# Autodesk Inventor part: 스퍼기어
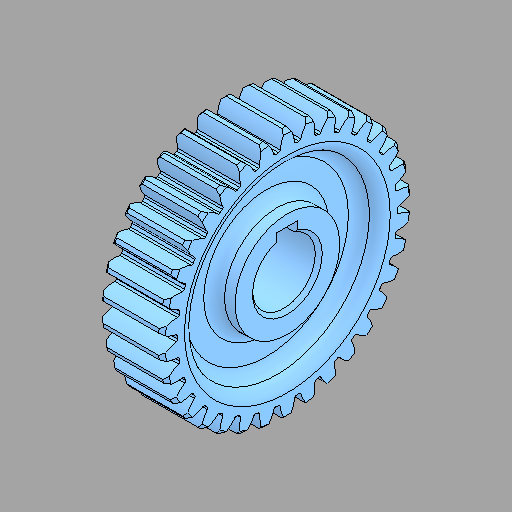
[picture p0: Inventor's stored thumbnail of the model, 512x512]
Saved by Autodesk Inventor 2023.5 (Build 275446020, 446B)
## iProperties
Created: 2025-07
Part Number: 스퍼기어
Material: 강철, 합금
Document SubType Name: Modeling
Designer: 1강의실14
Density: 7.73 g/cm^3
Appearance: 기본값
Author: jhkim
Sending System: Autodesk Inventor 2026
Preprocessor: ST-DEVELOPER v20.1
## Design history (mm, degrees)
feature "솔리드1"
node "솔리드2"
